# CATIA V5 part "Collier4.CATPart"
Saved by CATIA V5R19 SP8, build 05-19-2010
Part number: Collier4
Bounding box of the stored display mesh (mm): x -167.5 to -112.5, y 110.289 to 233.272, z 21.436 to 143.719
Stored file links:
  G:\EU_thinkMotion\CFAO_2010\MMS_groupe2\MMS_groupe2\A reprendre\jcauchy\Collier4.CATPart
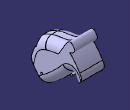
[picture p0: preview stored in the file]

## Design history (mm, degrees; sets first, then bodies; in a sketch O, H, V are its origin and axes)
Parameters
  Rayonfixation_collier4 = 2.5 mm
  Largeurcollier_collier4 = 55 mm
  Longueurfixation_collier4 = 20 mm
Set1
  Plane1: stored without definition
  Sketch1 on Plane1, origin (-120, 0, 0), H (0, 1, 0), V (0, 0, 1)
    spline S1 through (218.6285, 64.116) (225.4102, 66.3761) (231.2067, 72.4998)
    spline S2 through (231.2067, 72.4998) (233.2722, 79.9271) (229.1617, 90.0645)
    spline S3 through (229.1617, 90.0645) (219.2219, 104.8677) (205.1075, 120.8993)
    spline S4 through (205.1075, 120.8993) (212.1053, 123.8959) (217.0944, 129.7443) (213.871, 137.5642) (208.9702, 142.8039) (196.1274, 134.9278)
    spline S5 through (196.1274, 134.9278) (185.5772, 127.2831) (169.3172, 123.2835) (141.2617, 117.0056)
    spline S6 through (141.2617, 117.0056) (114.623, 100.0182) (103.4271, 78.7839)
    spline S7 through (103.4271, 78.7839) (125.0001, 41.8368) (145.6713, 21.4357)
    spline S8 through (218.6285, 64.116) (214.2949, 68.7475) (210.61, 72.9744)
    spline S9 through (210.61, 72.9744) (206.6161, 76.3294) (202.9042, 74.2945)
    spline S10 through (202.9042, 74.2945) (178.5538, 48.8165) (145.6713, 21.4357)
    point P1 (218.6285, 64.116)
    point P2 (231.2067, 72.4998)
    point P3 (231.2067, 72.4998)
    point P4 (229.1617, 90.0645)
    point P5 (229.1617, 90.0645)
    point P6 (205.1075, 120.8993)
    point P7 (205.1075, 120.8993)
    point P8 (196.1274, 134.9278)
    point P9 (196.1274, 134.9278)
    point P10 (141.2617, 117.0056)
    point P11 (141.2617, 117.0056)
    point P12 (103.4271, 78.7839)
    point P13 (103.4271, 78.7839)
    point P14 (145.6713, 21.4357)
    point P15 (218.6285, 64.116)
    point P16 (210.61, 72.9744)
    point P17 (210.61, 72.9744)
    point P18 (202.9042, 74.2945)
    point P19 (202.9042, 74.2945)
    point P20 (145.6713, 21.4357)
    coincidence: P2 P3, P4 P5, P6 P7, P8 P9, P10 P11, P12 P13, P15 P1, P16 P17, P18 P19, P20 P14
  DatumSurface1 to DatumSurface4
  Plane2: stored without definition
  DatumPoint1 to DatumPoint3
  Plane3: stored without definition
  DatumPoint4 to DatumPoint7
Body1 (main body)
  Pad1: profile Sketch1, direction (1, 0, 0), length 7.5 {= Largeurcollier_collier4 /2-Longueurfixation_collier4}, opposite side length 47.5 {= Largeurcollier_collier4 /2+Longueurfixation_collier4}
  Fillet1: radius 20, on edge [end face of Pad1 | face of Pad1 from Sketch1.S10]
  Fillet2: radius 20, on edge [face of Pad1 from Sketch1.S10 | start face of Pad1]
  Fillet3: radius 20, on edge [face of Pad1 from Sketch1.S5 | end face of Pad1]
  Fillet4: radius 20, on edge [start face of Pad1 | face of Pad1 from Sketch1.S5]
  Sketch2 on Plane2, origin (-120, 0, 0), H (0, 1, 0), V (0, 0, 1)
    circle A1 centre (206.9385, 74.349) radius 2.5
    point P1 (206.9385, 74.349)
    reference projected point E1 (206.9385, 74.349) from vertex of DatumPoint7
    radius A1 = 2.5 {= Rayonfixation_collier4}
    coincidence: P1 E1
  Pad2: profile Sketch2, direction (-1, 0, 0), length 20, opposite side length 5
  Sketch3 on end face of Pad2, origin (-140, 0, 0), H (0, -1, 0), V (0, 0, 1)
    line L1 (-220.4081, 81.4073) -> (-208.4471, 72.3555)
    arc A1 centre (-206.9385, 74.349) radius 2.5 from (-208.4471, 72.3555) to (-205.4298, 76.3425) ccw
    line L2 (-205.4298, 76.3425) -> (-217.3908, 85.3943)
    point P5 (-217.3908, 85.3943)
    line L3 (-217.3908, 85.3943) -> (-220.4081, 81.4073)
    point P6 (-217.3908, 85.3943)
    reference projected circle E1 centre (-206.9385, 74.349) radius 2.5 from edge [end face of Pad2 | face of Pad2 from Sketch2.A1]
    radius A1 = 2.5 {= Rayonfixation_collier4}
    length L2 = 15
    distance A1 E1 = 0
    tangency: A1 L1, L2 A1
    coincidence: P6 L2, P5 P6
    perpendicularity: L3 L1, L3 L2
  Pad3: profile Sketch3, direction (-1, 0, 0), length 4
  Body2
    Solid1: solid without history
  Remove1: tool Body2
